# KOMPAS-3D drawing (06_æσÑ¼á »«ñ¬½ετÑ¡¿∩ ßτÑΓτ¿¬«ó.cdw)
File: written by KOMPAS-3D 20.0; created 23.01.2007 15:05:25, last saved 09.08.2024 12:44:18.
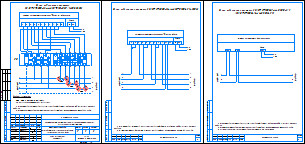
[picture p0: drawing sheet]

Sheets 1-3: A4, portrait

Document properties: Организация: ЗАО ИТФ "СИСТЕМЫ И ТЕХНОЛОГИИ"; Разработал: Антошин; Проверил: Тарасов; Утвердил: Шмончев; Н. контр.: Силаков; Форматы листов документа: 3xA4; Полное имя файла: \\s-tech\depts\Отдел_ПКО\Проекты\Типовые проекты МКД 2023\!Типовой проект\2_Типовой проект МКД_Радиоканал\06_Схема подключения счетчиков.cdw

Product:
- Part/product: (unnamed)
  - Component: \\Helios\отдел_пко\Общая папка Компас\_Addons\Signatures\Signatures.lfr|Тарасов  | Полное имя файла: C:\Users\MAntoshin\AppData\Local\Temp\qlkzkl.frw; source file: C:\Program Files\ASCON\KOMPAS-3D V13\Libs\_Addons\Signatures\Signatures.lfr
  - Component: \\Helios\отдел_пко\Общая папка Компас\_Addons\Signatures\Signatures.lfr|Силаков  | Полное имя файла: C:\Users\MAntoshin\AppData\Local\Temp\eiczbt.frw; source file: C:\Program Files\ASCON\KOMPAS-3D V13\Libs\_Addons\Signatures\Signatures.lfr
  - Component: \\Helios\отдел_пко\Общая папка Компас\_Addons\Signatures\Signatures.lfr|Шмончев  | Полное имя файла: C:\Users\MAntoshin\AppData\Local\Temp\hsklda.frw; source file: C:\Program Files\ASCON\KOMPAS-3D V13\Libs\_Addons\Signatures\Signatures.lfr

Title block, sheet 1: designation: ВЛСТ 1277.02.003 С5; sheet number: 1; Количество листов документа: 31; organisation: АО ГК / "Системы и Технологии"; Форматы листов документа: A4; stored path: C:\Program Files\ASCON\KOMPAS-3D V8 Plus\Templates\Чертеж строительный зданий и сооружений.cdt; cell 302: Система учета электроэнергии (с организацией удаленного / сбора данных) потребителей; cell 303: Типовой проект ИСУЭ / многоквартирного дома с использованием / радиоканала (F2/868 МГц); cell 304: Схема подключения счетчиков; cell 320: Р
Title block, sheet 2: sheet number: 2; stored path: \\Helios\Отдел_ПКО\Проекты\МРСК Северо-Запада Псковэнерго\Проект\02-07_Рабочая документация\03_Многоквартирный дом,Г.Псков, ул. Труда д. 16а\С5_003_Схема подключения счетчика ЦЭ 2727.cdw
Title block, sheet 3: sheet number: 3; stored path: \\Helios\отдел_пко\Проекты\МРСК Северо-Запада Псковэнерго\Типовой проект\С5_003_Схема подключения счетчика.cdw; designation, second copy: ВЛСТ 1277.02.003 С5-

Referenced files in \\Helios\отдел_пко\Общая папка Компас\_Addons\Signatures\: Signatures.lfr|Тарасов, Signatures.lfr, Signatures.lfr|Силаков, Signatures.lfr|Шмончев
Referenced files in C:\Program Files\ASCON\KOMPAS-3D V13\Libs\_Addons\Signatures\: Signatures.lfr
Referenced files: qlkzkl.frw, eiczbt.frw, hsklda.frw
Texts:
  Тарасов
  Силаков
  Шмончев
  Normal
  Разраб.
  Н.контр.
  Утв.
  Схема подключения
  счётчиков
  Антошин
  03 Рабочие чертежи основного комплекта. ГОСТ Р 21.1101-2009 Ф3
  05 Чертежи строительных изделий. Посл. листы.  ГОСТ 21.101-97 Ф6
Dimensions and other numbers on the sheet: 1; 31; 02.23; 3; 2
